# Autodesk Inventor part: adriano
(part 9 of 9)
sketch "スケッチ309"
  geometry: L1 (49.588, 51.125)-(25.588, 51.125); L2 (25.588, 51.125)-(25.588, 57.125); L3 (25.588, 57.125)-(49.588, 57.125); L4 (49.588, 57.125)-(49.588, 51.125); L5 (145.588, -37.314)-(139.588, -37.314); L6 (139.588, -37.314)-(139.588, -13.314); L7 (139.588, -13.314)-(145.588, -13.314); L8 (145.588, -13.314)-(145.588, -37.314); L9 (23.588, 40.686)-(23.588, 56.686) reference; L10 (137.588, -17.314)-(137.588, -55.314) reference; L11 (131.588, -17.314)-(137.588, -17.314) reference; 1 further point
  constraints: 16 end point, 4 parallel, 2 horizontal, 2 perpendicular
  dimensions: "d4627" = 6 distance of L3.end L1.start; "d4628" = 24 distance of L2.end L3.end; "d4629" = 2 distance between parallel lines of L9 L2; "d4630" = 2 distance between parallel lines of L10 L6; "d4631" = 24 distance of L7.end L5.start; "d4632" = 6 distance of L6.end L7.end; "d4633" = 4 distance between parallel lines of L7 L11
extrude "押し出し291" join sketch "スケッチ309" distance "d4634" = 6; taper "d4635" = 0 deg
fillet "フィレット27" dims "d4636" = 3
fillet "フィレット28" dims "d4637" = 2
fillet "フィレット29" dims "d4638" = 2
sketch "スケッチ310"
  geometry: L1 (144.588, -34.615)-(140.588, -34.615); L2 (140.588, -34.615)-(140.588, -28.615); L3 (140.588, -28.615)-(144.588, -28.615); L4 (144.588, -28.615)-(144.588, -34.615); L5 (144.588, -27.615)-(140.588, -27.615); L6 (140.588, -27.615)-(140.588, -16.314); L7 (140.588, -16.314)-(144.588, -16.314); L8 (144.588, -16.314)-(144.588, -27.615); L9 (145.588, -16.314)-(145.588, -35.314) reference; L10 (139.588, -35.314)-(139.588, -16.314) reference; L11 (33.588, 52.125)-(27.588, 52.125); L12 (27.588, 52.125)-(27.588, 56.125); L13 (27.588, 56.125)-(33.588, 56.125); L14 (33.588, 56.125)-(33.588, 52.125); L15 (46.588, 52.125)-(34.588, 52.125); L16 (34.588, 52.125)-(34.588, 56.125); L17 (34.588, 56.125)-(46.588, 56.125); L18 (46.588, 56.125)-(46.588, 52.125); L19 (46.588, 51.125)-(27.588, 51.125) reference; L20 (27.588, 57.125)-(46.588, 57.125) reference; 1 further point
  constraints: 32 end point, 8 parallel, 4 horizontal, 4 perpendicular, 4 point on line
  dimensions: "d4639" = 1 distance between parallel lines of L9 L4; "d4640" = 1 distance between parallel lines of L10 L2; "d4641" = 0 distance from line of L9.start L7; "d4642" = 1 distance between parallel lines of L5 L3; "d4643" = 6 distance of L3.end L1.start; "d4644" = 1 distance between parallel lines of L15 L19; "d4645" = 1 distance between parallel lines of L20 L17; "d4646" = 0 distance from line of L18 L19.start; "d4647" = 1 distance between parallel lines of L14 L16; "d4648" = 0 distance from line of L19.end L12; "d4649" = 6 distance of L11.start L11.end
extrude "押し出し292" cut sketch "スケッチ310" distance "d4650" = 2; taper "d4651" = 0 deg
sketch "スケッチ311"
  geometry: L1 (141.588, -16.314)-(141.588, -35.314) reference; L2 (143.588, -35.314)-(143.588, -16.314) reference; L3 (141.588, -33.615)-(143.588, -33.615); L4 (143.588, -33.615)-(143.588, -31.615); L5 (143.588, -31.615)-(141.588, -31.615); L6 (141.588, -31.615)-(141.588, -33.615); L7 (141.588, -25.615)-(143.588, -25.615); L8 (143.588, -25.615)-(143.588, -23.615); L9 (143.588, -23.615)-(141.588, -23.615); L10 (141.588, -23.615)-(141.588, -25.615); L11 (144.588, -34.615)-(140.588, -34.615) reference; L12 (144.588, -27.615)-(140.588, -27.615) reference; L13 (27.588, 53.125)-(46.588, 53.125) reference; L14 (46.588, 55.125)-(27.588, 55.125) reference; L15 (30.588, 53.125)-(28.588, 53.125); L16 (28.588, 53.125)-(28.588, 55.125); L17 (28.588, 55.125)-(30.588, 55.125); L18 (30.588, 55.125)-(30.588, 53.125); L19 (37.588, 53.125)-(35.588, 53.125); L20 (35.588, 53.125)-(35.588, 55.125); L21 (35.588, 55.125)-(37.588, 55.125); L22 (37.588, 55.125)-(37.588, 53.125); L23 (34.588, 52.125)-(34.588, 56.125) reference; L24 (27.588, 52.125)-(27.588, 56.125) reference; 1 further point
  constraints: 32 end point, 8 parallel, 8 point on line, 4 horizontal, 4 perpendicular
  dimensions: "d4652" = 1 distance between parallel lines of L11 L3; "d4653" = 2 distance between parallel lines of L5 L3; "d4654" = 2 distance between parallel lines of L9 L7; "d4655" = 2 distance between parallel lines of L7 L12; "d4656" = 2 distance between parallel lines of L18 L16; "d4657" = 2 distance between parallel lines of L20 L22; "d4658" = 1 distance between parallel lines of L23 L20; "d4659" = 1 distance between parallel lines of L24 L16
extrude "押し出し293" join sketch "スケッチ311" distance "d4660" = 3; taper "d4661" = 0 deg
sketch "スケッチ312"
  geometry: L1 (0.8, 39.2)-(1.6, 39.2); L2 (1.6, 39.2)-(1.6, 36.8); L3 (1.6, 36.8)-(0.8, 36.8); L4 (0.8, 36.8)-(0.8, 39.2); L5 (2.4, 39.2)-(3.2, 39.2); L6 (3.2, 39.2)-(3.2, 36.8); L7 (3.2, 36.8)-(2.4, 36.8); L8 (2.4, 36.8)-(2.4, 39.2); L9 (4, 39.2)-(4.8, 39.2); L10 (4.8, 39.2)-(4.8, 36.8); L11 (4.8, 36.8)-(4, 36.8); L12 (4, 36.8)-(4, 39.2); L13 (5.6, 39.2)-(6.4, 39.2); L14 (6.4, 39.2)-(6.4, 36.8); L15 (6.4, 36.8)-(5.6, 36.8); L16 (5.6, 36.8)-(5.6, 39.2); L17 (7.2, 39.2)-(8, 39.2); L18 (8, 39.2)-(8, 36.8); L19 (8, 36.8)-(7.2, 36.8); L20 (7.2, 36.8)-(7.2, 39.2); L21 (8.8, 39.2)-(9.6, 39.2); L22 (9.6, 39.2)-(9.6, 36.8); L23 (9.6, 36.8)-(8.8, 36.8); L24 (8.8, 36.8)-(8.8, 39.2); L25 (25, 20)-(41, 20) reference; L26 (0, 40)-(19, 40) reference; L27 (0, 0)-(0, 40) reference; L28 (10.4, 39.2)-(11.2, 39.2); L29 (11.2, 39.2)-(11.2, 36.8); L30 (11.2, 36.8)-(10.4, 36.8); L31 (10.4, 36.8)-(10.4, 39.2); L32 (12, 39.2)-(12.8, 39.2); L33 (12.8, 39.2)-(12.8, 36.8); L34 (12.8, 36.8)-(12, 36.8); L35 (12, 36.8)-(12, 39.2); L36 (13.6, 39.2)-(14.4, 39.2); L37 (14.4, 39.2)-(14.4, 36.8); L38 (14.4, 36.8)-(13.6, 36.8); L39 (13.6, 36.8)-(13.6, 39.2); L40 (15.2, 39.2)-(16, 39.2); L41 (16, 39.2)-(16, 36.8); L42 (16, 36.8)-(15.2, 36.8); L43 (15.2, 36.8)-(15.2, 39.2); L44 (16.8, 39.2)-(17.6, 39.2); L45 (17.6, 39.2)-(17.6, 36.8); L46 (17.6, 36.8)-(16.8, 36.8); L47 (16.8, 36.8)-(16.8, 39.2); L48 (18, 36)-(0, 36) reference; 1 further point
  constraints: 88 end point, 22 parallel, 18 point on line, 11 horizontal, 11 perpendicular
  dimensions: "d4662" = 0.8 distance of L2.end L3.end; "d4663" = 0.8 distance of L6.end L7.end; "d4664" = 0.8 distance of L10.end L11.end; "d4665" = 0.8 distance of L14.end L15.end; "d4666" = 0.8 distance of L18.end L19.end; "d4667" = 0.8 distance of L22.end L23.end; "d4668" = 0.8 distance between parallel lines of L8 L2; "d4669" = 0.8 distance between parallel lines of L12 L6; "d4670" = 0.8 distance between parallel lines of L16 L10; "d4671" = 0.8 distance between parallel lines of L14 L20; "d4672" = 0.8 distance between parallel lines of L24 L18; "d4673" = 2.4 distance of L3.end L1.start; "d4675" = 0.8 distance between parallel lines of L1 L26; "d4676" = 0.8 distance between parallel lines of L4 L27; "d4677" = 0.8 distance between parallel lines of L31 L22; "d4678" = 0.8 distance between parallel lines of L48 L30; "d4679" = 0.8 distance of L29.end L30.end; "d4680" = 0.8 distance between parallel lines of L35 L29; "d4681" = 0.8 distance of L33.end L34.end; "d4682" = 0.8 distance between parallel lines of L39 L33; "d4683" = 0.8 distance of L37.end L38.end; "d4684" = 0.8 distance from line of L42.end L37; "d4685" = 0.8 distance of L41.end L42.end; "d4686" = 0.8 distance between parallel lines of L47 L41; "d4687" = 0.8 distance of L45.end L46.end
extrude "押し出し294" cut sketch "スケッチ312" distance "d4688" = 2; taper "d4689" = 0 deg
sketch "スケッチ313"
  geometry: L1 (-101.412, 0.686)-(-105.412, 0.686); L2 (-105.412, 0.686)-(-105.412, 24.686); L3 (-105.412, 24.686)-(-101.412, 24.686); L4 (-101.412, 24.686)-(-101.412, 0.686); L5 (-95.412, 10.686)-(-95.412, 6.686) reference; L6 (-95.412, 6.686)-(-79.412, 6.686) reference; 1 further point
  constraints: 8 end point, 2 parallel, 1 horizontal, 1 perpendicular
  dimensions: "d4690" = 4 distance of L2.end L3.end; "d4691" = 6 distance between parallel lines of L4 L5; "d4692" = 6 distance between parallel lines of L1 L6; "d4693" = 24 distance of L1.end L2.end
extrude "押し出し295" join sketch "スケッチ313" stored distance "d4694" = 4; taper "d4695" = 0 deg
fillet "フィレット30" dims "d4696" = 2
node "作業平面4"
sketch "スケッチ314"
  geometry: L1 (-87.412, 8.686)-(-87.412, 12.686); L2 (-87.412, 12.686)-(-103.412, 8.686); L3 (-103.412, 8.686)-(-119.412, 12.686); L4 (-119.412, 12.686)-(-119.412, 8.686); L5 (-119.412, 8.686)-(-103.412, 4.686); L6 (-103.412, 4.686)-(-87.412, 8.686); L7 (-103.412, 0.686)-(-103.412, 2.686) reference; L8 (-79.412, -16.314)-(-79.412, 10.686) reference; 1 further point
  constraints: 12 end point, 1 parallel, 1 vertical
  dimensions: "d4698" = 32 distance between parallel lines of L4 L1; "d4699" = 0 distance from line of L5.end L7; "d4701" = 0 horizontal distance of L2.end L5.end; "d4702" = 0 vertical distance of L3.end L1.end; "d4703" = 2 distance of L5.end L7.end; "d4704" = 4 distance of L5.end L2.end; "d4705" = 16 distance from line of L2.end L1; "d4706" = 4 vertical distance of L4.end L5.end; "d4707" = 0 vertical distance of L4.end L1.start; "d4708" = 4 distance of L1.start L1.end
extrude "押し出し296" join sketch "スケッチ314" distance "d4709" = 1; taper "d4710" = 0 deg
sketch "スケッチ315"
  geometry: L1 (-95.412, 24.098)-(-95.412, 21.098); L2 (-95.412, 21.098)-(-103.337, 19.098); L3 (-103.337, 19.098)-(-111.412, 21.098); L4 (-111.412, 21.098)-(-111.412, 24.098); L5 (-111.412, 24.098)-(-103.337, 22.098); L6 (-103.337, 22.098)-(-95.412, 24.098); L7 (-87.412, 8.686)-(-87.412, 12.686) reference; 1 further point
  constraints: 12 end point, 2 parallel, 1 vertical
  dimensions: "d4711" = 16 distance between parallel lines of L4 L1; "d4712" = 8 distance between parallel lines of L1 L7; "d4713" = 0 vertical distance of L3.end L1.end; "d4714" = 0 vertical distance of L4.end L1.start; "d4715" = 3 distance of L3.end L4.end; "d4716" = 2 vertical distance of L3.end L2.end; "d4717" = 3 distance of L5.end L2.end
extrude "押し出し297" join sketch "スケッチ315" distance "d4718" = 1; taper "d4719" = 0 deg
sketch "スケッチ316"
  geometry: L1 (-102.912, 20.098)-(-103.912, 20.098); L2 (-103.912, 20.098)-(-103.912, 23.098); L3 (-103.912, 23.098)-(-102.912, 23.098); L4 (-102.912, 23.098)-(-102.912, 20.098); L5 (-95.412, 21.098)-(-95.412, 24.098) reference; 1 further point
  constraints: 8 end point, 2 parallel, 1 horizontal, 1 perpendicular
  dimensions: "d4720" = 3 distance of L1.end L2.end; "d4721" = 7.5 distance between parallel lines of L5 L4; "d4722" = 1 distance of L2.end L3.end; "d4723" = 1 distance from line of L5.end L3
extrude "押し出し298" join sketch "スケッチ316" distance "d4724" = 6; taper "d4725" = 0 deg
sketch "スケッチ317"
  geometry: L1 (-24, 2)-(-24, 3) reference; L2 (8, 2)-(8, 3) reference; C1 r 1 at (4, 1.077); C2 r 1 at (-20, 1.077); 1 further point
  constraints: 2 centre point
  dimensions: "d4726" = 4 distance from line of C2.centre L1; "d4727" = 4 distance from line of C1.centre L2; "d4728" = 2 diameter of C1; "d4729" = 2 diameter of C2
extrude "押し出し299" join sketch "スケッチ317" distance "d4730" = 6; taper "d4731" = 0 deg
sketch "スケッチ318"
  geometry: L1 (-8, 3)-(8, 3) reference; C1 r 2 at (-7.963, 6); 1 further point
  constraints: 1 centre point
  dimensions: "d4732" = 3 distance from line of L1 C1.centre; "d4733" = 4 diameter of C1
extrude "押し出し300" join sketch "スケッチ318" stored distance "d4734" = 6; taper "d4735" = 0 deg
fillet "フィレット31" dims "d4736" = 2
fillet "フィレット32" dims "d4737" = 2
fillet "フィレット33" dims "d4738" = 1
node "ソリッド1"
other parameters: "d4463" = -4, "d4467" = -8, "d4496" = -1, "d4697" = 2
